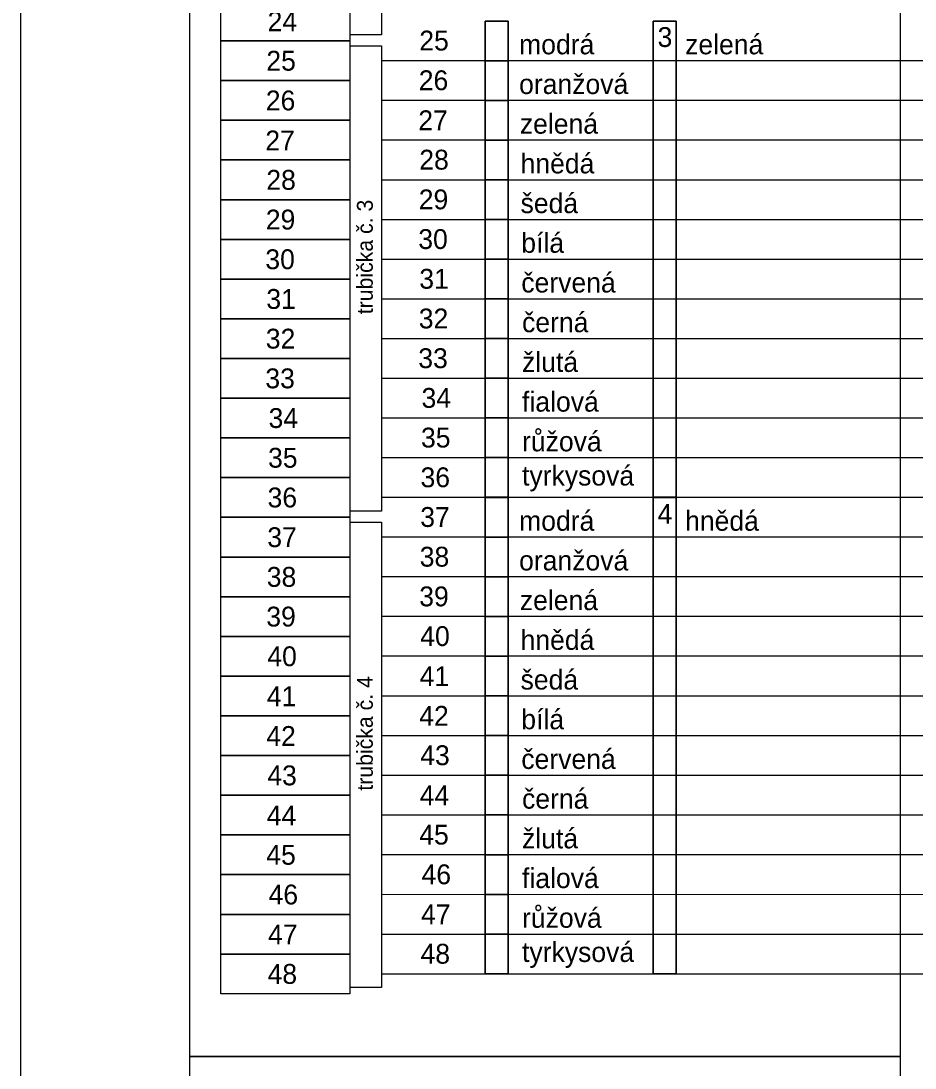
# Model space of a CAD drawing. Extents: x 1901 to 2519, y -3585 to -3154.
# Drawn here: x 1901.2 to 1980.5, y -3380.3 to -3287.5 of the extents above; entities that cross this region are included whole.
import ezdxf

# ---------------------------------------------------------------- set-up
doc = ezdxf.new("R2010")
doc.units = 0
doc.layers.add('rozvláknění', color=7, linetype='Continuous')
doc.layers.add('Vrstva 4', color=7, linetype='Continuous')

msp = doc.modelspace()

# ---------------------------------------------------------------- linework, layer by layer
at = {"layer": 'rozvláknění'}
for p, q in [((1930.388, -3287.484), (1930.406, -3287.484)), ((1930.388, -3291.004), (1930.406, -3291.004)), ((1933.193, -3290.983), (2025.898, -3290.985)), ((1930.388, -3294.524), (1930.406, -3294.524)), ((1933.193, -3294.501), (2025.898, -3294.503)), ((1930.388, -3298.044), (1930.406, -3298.044)), ((1933.193, -3298.019), (2025.898, -3298.021)), ((1933.193, -3298.044), (1933.193, -3301.564)), ((1930.388, -3301.564), (1930.406, -3301.564)), ((1933.193, -3301.559), (2025.898, -3301.561)), ((1930.388, -3305.084), (1930.406, -3305.084)), ((1933.193, -3305.077), (2025.898, -3305.079)), ((1930.388, -3308.604), (1930.406, -3308.604)), ((1933.193, -3308.595), (2025.898, -3308.597)), ((1933.193, -3308.604), (1933.193, -3312.124)), ((1930.388, -3312.124), (1930.406, -3312.124)), ((1933.193, -3312.114), (2025.898, -3312.116)), ((1930.388, -3315.644), (1930.406, -3315.644)), ((1933.193, -3315.632), (2025.898, -3315.634)), ((1930.388, -3319.164), (1930.406, -3319.164)), ((1933.193, -3319.15), (2025.898, -3319.152)), ((1933.193, -3319.164), (1933.193, -3322.684)), ((1930.388, -3322.684), (1930.406, -3322.684)), ((1933.193, -3322.668), (2025.898, -3322.67)), ((1930.388, -3326.204), (1930.406, -3326.204)), ((1933.193, -3326.186), (2025.898, -3326.188)), ((1930.388, -3329.724), (1930.406, -3329.724)), ((1933.193, -3329.705), (2025.898, -3329.707)), ((1930.388, -3333.244), (1930.406, -3333.244)), ((1933.193, -3333.223), (2025.898, -3333.225)), ((1930.388, -3336.764), (1930.406, -3336.764)), ((1933.193, -3336.741), (2025.898, -3336.743)), ((1930.388, -3340.284), (1930.406, -3340.284)), ((1933.193, -3340.259), (2025.898, -3340.261)), ((1933.193, -3340.284), (1933.193, -3343.804)), ((1930.388, -3343.804), (1930.406, -3343.804)), ((1933.193, -3343.777), (2025.898, -3343.779)), ((1930.388, -3347.324), (1930.406, -3347.324)), ((1933.193, -3347.296), (2025.898, -3347.298)), ((1930.388, -3350.844), (1930.406, -3350.844)), ((1933.193, -3350.835), (2025.898, -3350.837)), ((1933.193, -3350.844), (1933.193, -3354.364)), ((1930.388, -3354.364), (1930.406, -3354.364)), ((1933.193, -3354.354), (2025.898, -3354.356)), ((1930.388, -3357.884), (1930.406, -3357.884)), ((1933.193, -3357.872), (2025.898, -3357.874)), ((1930.388, -3361.404), (1930.406, -3361.404)), ((1933.193, -3361.39), (2025.898, -3361.392)), ((1933.193, -3361.404), (1933.193, -3364.924)), ((1930.388, -3364.924), (1930.406, -3364.924)), ((1933.193, -3364.908), (2025.898, -3364.91)), ((1930.388, -3368.444), (1930.406, -3368.444)), ((1933.193, -3368.426), (2025.898, -3368.428)), ((1930.388, -3371.964), (1930.406, -3371.964)), ((1933.193, -3371.945), (2025.898, -3371.947))]:
    msp.add_line(p, q, dxfattribs=at)
for points in [[(1916.214, -3178.545), (1979.2, -3178.544), (1979.2, -3379.278), (1916.214, -3379.278)], [(1930.406, -3247.439), (1933.193, -3247.439), (1933.193, -3288.698), (1930.406, -3288.698)], [(1918.946, -3285.724), (1930.388, -3285.724), (1930.388, -3289.244), (1918.946, -3289.244)], [(1942.405, -3287.488), (1944.446, -3287.488), (1944.446, -3291.007), (1942.405, -3291.007)], [(1959.324, -3329.707), (1957.283, -3329.707), (1957.283, -3287.488), (1959.324, -3287.488)], [(1918.946, -3289.244), (1930.388, -3289.244), (1930.388, -3292.764), (1918.946, -3292.764)], [(1930.406, -3289.679), (1933.193, -3289.679), (1933.193, -3330.938), (1930.406, -3330.938)], [(1942.405, -3291.007), (1944.446, -3291.007), (1944.446, -3294.525), (1942.405, -3294.525)], [(1918.946, -3292.764), (1930.388, -3292.764), (1930.388, -3296.284), (1918.946, -3296.284)], [(1942.405, -3294.525), (1944.446, -3294.525), (1944.446, -3298.043), (1942.405, -3298.043)], [(1918.946, -3296.284), (1930.388, -3296.284), (1930.388, -3299.804), (1918.946, -3299.804)], [(1942.405, -3298.043), (1944.446, -3298.043), (1944.446, -3301.561), (1942.405, -3301.561)], [(1918.946, -3299.804), (1930.388, -3299.804), (1930.388, -3303.324), (1918.946, -3303.324)], [(1942.405, -3301.561), (1944.446, -3301.561), (1944.446, -3305.079), (1942.405, -3305.079)], [(1918.946, -3303.324), (1930.388, -3303.324), (1930.388, -3306.844), (1918.946, -3306.844)], [(1942.405, -3305.079), (1944.446, -3305.079), (1944.446, -3308.597), (1942.405, -3308.597)], [(1918.946, -3306.844), (1930.388, -3306.844), (1930.388, -3310.364), (1918.946, -3310.364)], [(1942.405, -3308.597), (1944.446, -3308.597), (1944.446, -3312.116), (1942.405, -3312.116)], [(1918.946, -3310.364), (1930.388, -3310.364), (1930.388, -3313.884), (1918.946, -3313.884)], [(1942.405, -3312.116), (1944.446, -3312.116), (1944.446, -3315.634), (1942.405, -3315.634)], [(1918.946, -3313.884), (1930.388, -3313.884), (1930.388, -3317.404), (1918.946, -3317.404)], [(1942.405, -3315.634), (1944.446, -3315.634), (1944.446, -3319.152), (1942.405, -3319.152)], [(1918.946, -3317.404), (1930.388, -3317.404), (1930.388, -3320.924), (1918.946, -3320.924)], [(1942.405, -3319.152), (1944.446, -3319.152), (1944.446, -3322.67), (1942.405, -3322.67)], [(1918.946, -3320.924), (1930.388, -3320.924), (1930.388, -3324.444), (1918.946, -3324.444)], [(1942.405, -3322.67), (1944.446, -3322.67), (1944.446, -3326.188), (1942.405, -3326.188)], [(1918.946, -3324.444), (1930.388, -3324.444), (1930.388, -3327.964), (1918.946, -3327.964)], [(1942.405, -3326.188), (1944.446, -3326.188), (1944.446, -3329.707), (1942.405, -3329.707)], [(1918.946, -3327.964), (1930.388, -3327.964), (1930.388, -3331.484), (1918.946, -3331.484)], [(1942.405, -3329.728), (1944.446, -3329.728), (1944.446, -3333.247), (1942.405, -3333.247)], [(1959.324, -3371.947), (1957.283, -3371.947), (1957.283, -3329.728), (1959.324, -3329.728)], [(1918.946, -3331.484), (1930.388, -3331.484), (1930.388, -3335.004), (1918.946, -3335.004)], [(1930.406, -3331.919), (1933.193, -3331.919), (1933.193, -3373.178), (1930.406, -3373.178)], [(1942.405, -3333.247), (1944.446, -3333.247), (1944.446, -3336.765), (1942.405, -3336.765)], [(1918.946, -3335.004), (1930.388, -3335.004), (1930.388, -3338.524), (1918.946, -3338.524)], [(1942.405, -3336.765), (1944.446, -3336.765), (1944.446, -3340.283), (1942.405, -3340.283)], [(1918.946, -3338.524), (1930.388, -3338.524), (1930.388, -3342.044), (1918.946, -3342.044)], [(1942.405, -3340.283), (1944.446, -3340.283), (1944.446, -3343.801), (1942.405, -3343.801)], [(1918.946, -3342.044), (1930.388, -3342.044), (1930.388, -3345.564), (1918.946, -3345.564)], [(1942.405, -3343.801), (1944.446, -3343.801), (1944.446, -3347.319), (1942.405, -3347.319)], [(1918.946, -3345.564), (1930.388, -3345.564), (1930.388, -3349.084), (1918.946, -3349.084)], [(1942.405, -3347.319), (1944.446, -3347.319), (1944.446, -3350.837), (1942.405, -3350.837)], [(1918.946, -3349.084), (1930.388, -3349.084), (1930.388, -3352.604), (1918.946, -3352.604)], [(1942.405, -3350.837), (1944.446, -3350.837), (1944.446, -3354.356), (1942.405, -3354.356)], [(1918.946, -3352.604), (1930.388, -3352.604), (1930.388, -3356.124), (1918.946, -3356.124)], [(1942.405, -3354.356), (1944.446, -3354.356), (1944.446, -3357.874), (1942.405, -3357.874)], [(1918.946, -3356.124), (1930.388, -3356.124), (1930.388, -3359.644), (1918.946, -3359.644)], [(1942.405, -3357.874), (1944.446, -3357.874), (1944.446, -3361.392), (1942.405, -3361.392)], [(1918.946, -3359.644), (1930.388, -3359.644), (1930.388, -3363.164), (1918.946, -3363.164)], [(1942.405, -3361.392), (1944.446, -3361.392), (1944.446, -3364.91), (1942.405, -3364.91)], [(1918.946, -3363.164), (1930.388, -3363.164), (1930.388, -3366.684), (1918.946, -3366.684)], [(1942.405, -3364.91), (1944.446, -3364.91), (1944.446, -3368.428), (1942.405, -3368.428)], [(1918.946, -3366.684), (1930.388, -3366.684), (1930.388, -3370.204), (1918.946, -3370.204)], [(1942.405, -3368.428), (1944.446, -3368.428), (1944.446, -3371.947), (1942.405, -3371.947)], [(1918.946, -3370.204), (1930.388, -3370.204), (1930.388, -3373.724), (1918.946, -3373.724)], [(1916.214, -3379.278), (1979.2, -3379.277), (1979.2, -3570.656), (1916.214, -3570.656)]]:
    msp.add_lwpolyline(points, close=True, dxfattribs=at)
for points in [[(1942.405, -3291.007), (1944.446, -3291.007), (1944.446, -3287.488), (1942.405, -3287.488), (1942.405, -3291.007)], [(1959.324, -3287.488), (1957.283, -3287.488), (1957.283, -3329.707), (1959.324, -3329.707), (1959.324, -3287.488)], [(1942.405, -3294.525), (1944.446, -3294.525), (1944.446, -3291.007), (1942.405, -3291.007), (1942.405, -3294.525)], [(1942.405, -3298.043), (1944.446, -3298.043), (1944.446, -3294.525), (1942.405, -3294.525), (1942.405, -3298.043)], [(1942.405, -3301.561), (1944.446, -3301.561), (1944.446, -3298.043), (1942.405, -3298.043), (1942.405, -3301.561)], [(1942.405, -3305.079), (1944.446, -3305.079), (1944.446, -3301.561), (1942.405, -3301.561), (1942.405, -3305.079)], [(1942.405, -3308.597), (1944.446, -3308.597), (1944.446, -3305.079), (1942.405, -3305.079), (1942.405, -3308.597)], [(1942.405, -3312.116), (1944.446, -3312.116), (1944.446, -3308.597), (1942.405, -3308.597), (1942.405, -3312.116)], [(1942.405, -3315.634), (1944.446, -3315.634), (1944.446, -3312.116), (1942.405, -3312.116), (1942.405, -3315.634)], [(1942.405, -3319.152), (1944.446, -3319.152), (1944.446, -3315.634), (1942.405, -3315.634), (1942.405, -3319.152)], [(1942.405, -3322.67), (1944.446, -3322.67), (1944.446, -3319.152), (1942.405, -3319.152), (1942.405, -3322.67)], [(1942.405, -3326.188), (1944.446, -3326.188), (1944.446, -3322.67), (1942.405, -3322.67), (1942.405, -3326.188)], [(1942.405, -3329.707), (1944.446, -3329.707), (1944.446, -3326.188), (1942.405, -3326.188), (1942.405, -3329.707)], [(1942.405, -3333.247), (1944.446, -3333.247), (1944.446, -3329.728), (1942.405, -3329.728), (1942.405, -3333.247)], [(1959.324, -3329.728), (1957.283, -3329.728), (1957.283, -3371.947), (1959.324, -3371.947), (1959.324, -3329.728)], [(1942.405, -3336.765), (1944.446, -3336.765), (1944.446, -3333.247), (1942.405, -3333.247), (1942.405, -3336.765)], [(1942.405, -3340.283), (1944.446, -3340.283), (1944.446, -3336.765), (1942.405, -3336.765), (1942.405, -3340.283)], [(1942.405, -3343.801), (1944.446, -3343.801), (1944.446, -3340.283), (1942.405, -3340.283), (1942.405, -3343.801)], [(1942.405, -3347.319), (1944.446, -3347.319), (1944.446, -3343.801), (1942.405, -3343.801), (1942.405, -3347.319)], [(1942.405, -3350.837), (1944.446, -3350.837), (1944.446, -3347.319), (1942.405, -3347.319), (1942.405, -3350.837)], [(1942.405, -3354.356), (1944.446, -3354.356), (1944.446, -3350.837), (1942.405, -3350.837), (1942.405, -3354.356)], [(1942.405, -3357.874), (1944.446, -3357.874), (1944.446, -3354.356), (1942.405, -3354.356), (1942.405, -3357.874)], [(1942.405, -3361.392), (1944.446, -3361.392), (1944.446, -3357.874), (1942.405, -3357.874), (1942.405, -3361.392)], [(1942.405, -3364.91), (1944.446, -3364.91), (1944.446, -3361.392), (1942.405, -3361.392), (1942.405, -3364.91)], [(1942.405, -3368.428), (1944.446, -3368.428), (1944.446, -3364.91), (1942.405, -3364.91), (1942.405, -3368.428)], [(1942.405, -3371.947), (1944.446, -3371.947), (1944.446, -3368.428), (1942.405, -3368.428), (1942.405, -3371.947)]]:
    msp.add_lwpolyline(points, dxfattribs=at)
at = {"layer": 'Vrstva 4'}
msp.add_lwpolyline([(1901.224, -3154.468), (2516.224, -3154.468), (2516.224, -3584.968), (1901.224, -3584.968)], close=True, dxfattribs=at)

# ---------------------------------------------------------------- texts
at = {"layer": 'rozvláknění'}
for s, p in [('24', (1923.096, -3288.393)), ('3', (1957.681, -3289.784)), ('25', (1936.55, -3290.095)), ('modrá', (1945.401, -3290.433)), ('zelená', (1960.122, -3290.433)), ('25', (1922.986, -3291.884)), ('26', (1936.503, -3293.615)), ('oranžová', (1945.401, -3293.953)), ('26', (1922.939, -3295.404)), ('27', (1936.461, -3297.165)), ('zelená', (1945.467, -3297.473)), ('27', (1922.897, -3298.953)), ('28', (1936.55, -3300.655)), ('hnědá', (1945.532, -3300.993)), ('28', (1922.986, -3302.444)), ('29', (1936.503, -3304.175)), ('šedá', (1945.532, -3304.513)), ('29', (1922.939, -3305.964)), ('30', (1936.461, -3307.695)), ('bílá', (1945.597, -3308.033)), ('30', (1922.897, -3309.484)), ('31', (1936.55, -3311.215)), ('červená', (1945.597, -3311.553)), ('31', (1922.986, -3313.004)), ('32', (1936.503, -3314.735)), ('černá', (1945.663, -3315.073)), ('32', (1922.939, -3316.524)), ('33', (1936.461, -3318.255)), ('žlutá', (1945.663, -3318.593)), ('33', (1922.897, -3320.044)), ('34', (1936.749, -3321.775)), ('fialová', (1945.663, -3322.113)), ('34', (1923.185, -3323.564)), ('35', (1936.702, -3325.295)), ('růžová', (1945.663, -3325.633)), ('35', (1923.138, -3327.084)), ('36', (1936.66, -3328.815)), ('tyrkysová', (1945.663, -3328.665)), ('36', (1923.096, -3330.604)), ('37', (1936.635, -3332.335)), ('modrá', (1945.401, -3332.673)), ('4', (1957.681, -3332.054)), ('hnědá', (1960.122, -3332.673)), ('37', (1923.072, -3334.124)), ('38', (1936.588, -3335.855)), ('oranžová', (1945.401, -3336.193)), ('38', (1923.025, -3337.644)), ('39', (1936.546, -3339.375)), ('zelená', (1945.467, -3339.713)), ('39', (1922.983, -3341.164)), ('40', (1936.635, -3342.895)), ('hnědá', (1945.532, -3343.233)), ('40', (1923.072, -3344.684)), ('41', (1936.588, -3346.445)), ('šedá', (1945.532, -3346.753)), ('41', (1923.025, -3348.233)), ('42', (1936.546, -3349.965)), ('bílá', (1945.597, -3350.273)), ('42', (1922.983, -3351.753)), ('43', (1936.635, -3353.455)), ('červená', (1945.597, -3353.793)), ('43', (1923.072, -3355.244)), ('44', (1936.588, -3357.005)), ('černá', (1945.663, -3357.313)), ('44', (1923.025, -3358.793)), ('45', (1936.546, -3360.495)), ('žlutá', (1945.663, -3360.833)), ('45', (1922.983, -3362.284)), ('46', (1936.749, -3364.015)), ('fialová', (1945.663, -3364.353)), ('46', (1923.185, -3365.804)), ('47', (1936.702, -3367.565)), ('růžová', (1945.663, -3367.873)), ('47', (1923.138, -3369.353)), ('48', (1936.66, -3371.055)), ('tyrkysová', (1945.663, -3370.905)), ('48', (1923.096, -3372.844))]:
    msp.add_text(s, height=1.76, dxfattribs=at).set_placement(p)
for s, p in [('trubička č. 3', (1932.427, -3313.477)), ('trubička č. 4', (1932.428, -3355.717))]:
    msp.add_text(s, height=1.408, rotation=90, dxfattribs=at).set_placement(p)

doc.saveas('drawing.dxf')
